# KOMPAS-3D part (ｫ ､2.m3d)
File: created 04.01.2016 18:05:13, last saved 27.07.2016 13:38:10.
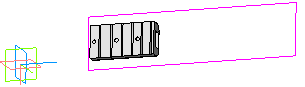
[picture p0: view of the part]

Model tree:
1. Эскиз:1
2. Операция выдавливания:1
     Расстояние 1 = 20
3. Эскиз:2
4. Операция выдавливания:2
     Расстояние 1 = 400
5. Эскиз:3
6. Вырезать элемент выдавливания:1
     Расстояние 1 = 70
7. Эскиз:4
8. Вырезать элемент выдавливания:2
     Расстояние 1 = 2
9. Эскиз:5
10. Эскиз:6
11. Вырезать элемент выдавливания:3
     Расстояние 2 = 40; Расстояние 1 = 36
12. Эскиз:7
13. Вырезать элемент выдавливания:4
     Расстояние 1 = 50
14. Эскиз:8
15. Эскиз:9
16. Вырезать элемент выдавливания:5
     Расстояние 1 = 30
17. Эскиз:10
18. Вырезать элемент выдавливания:6
     Расстояние 1 = 30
